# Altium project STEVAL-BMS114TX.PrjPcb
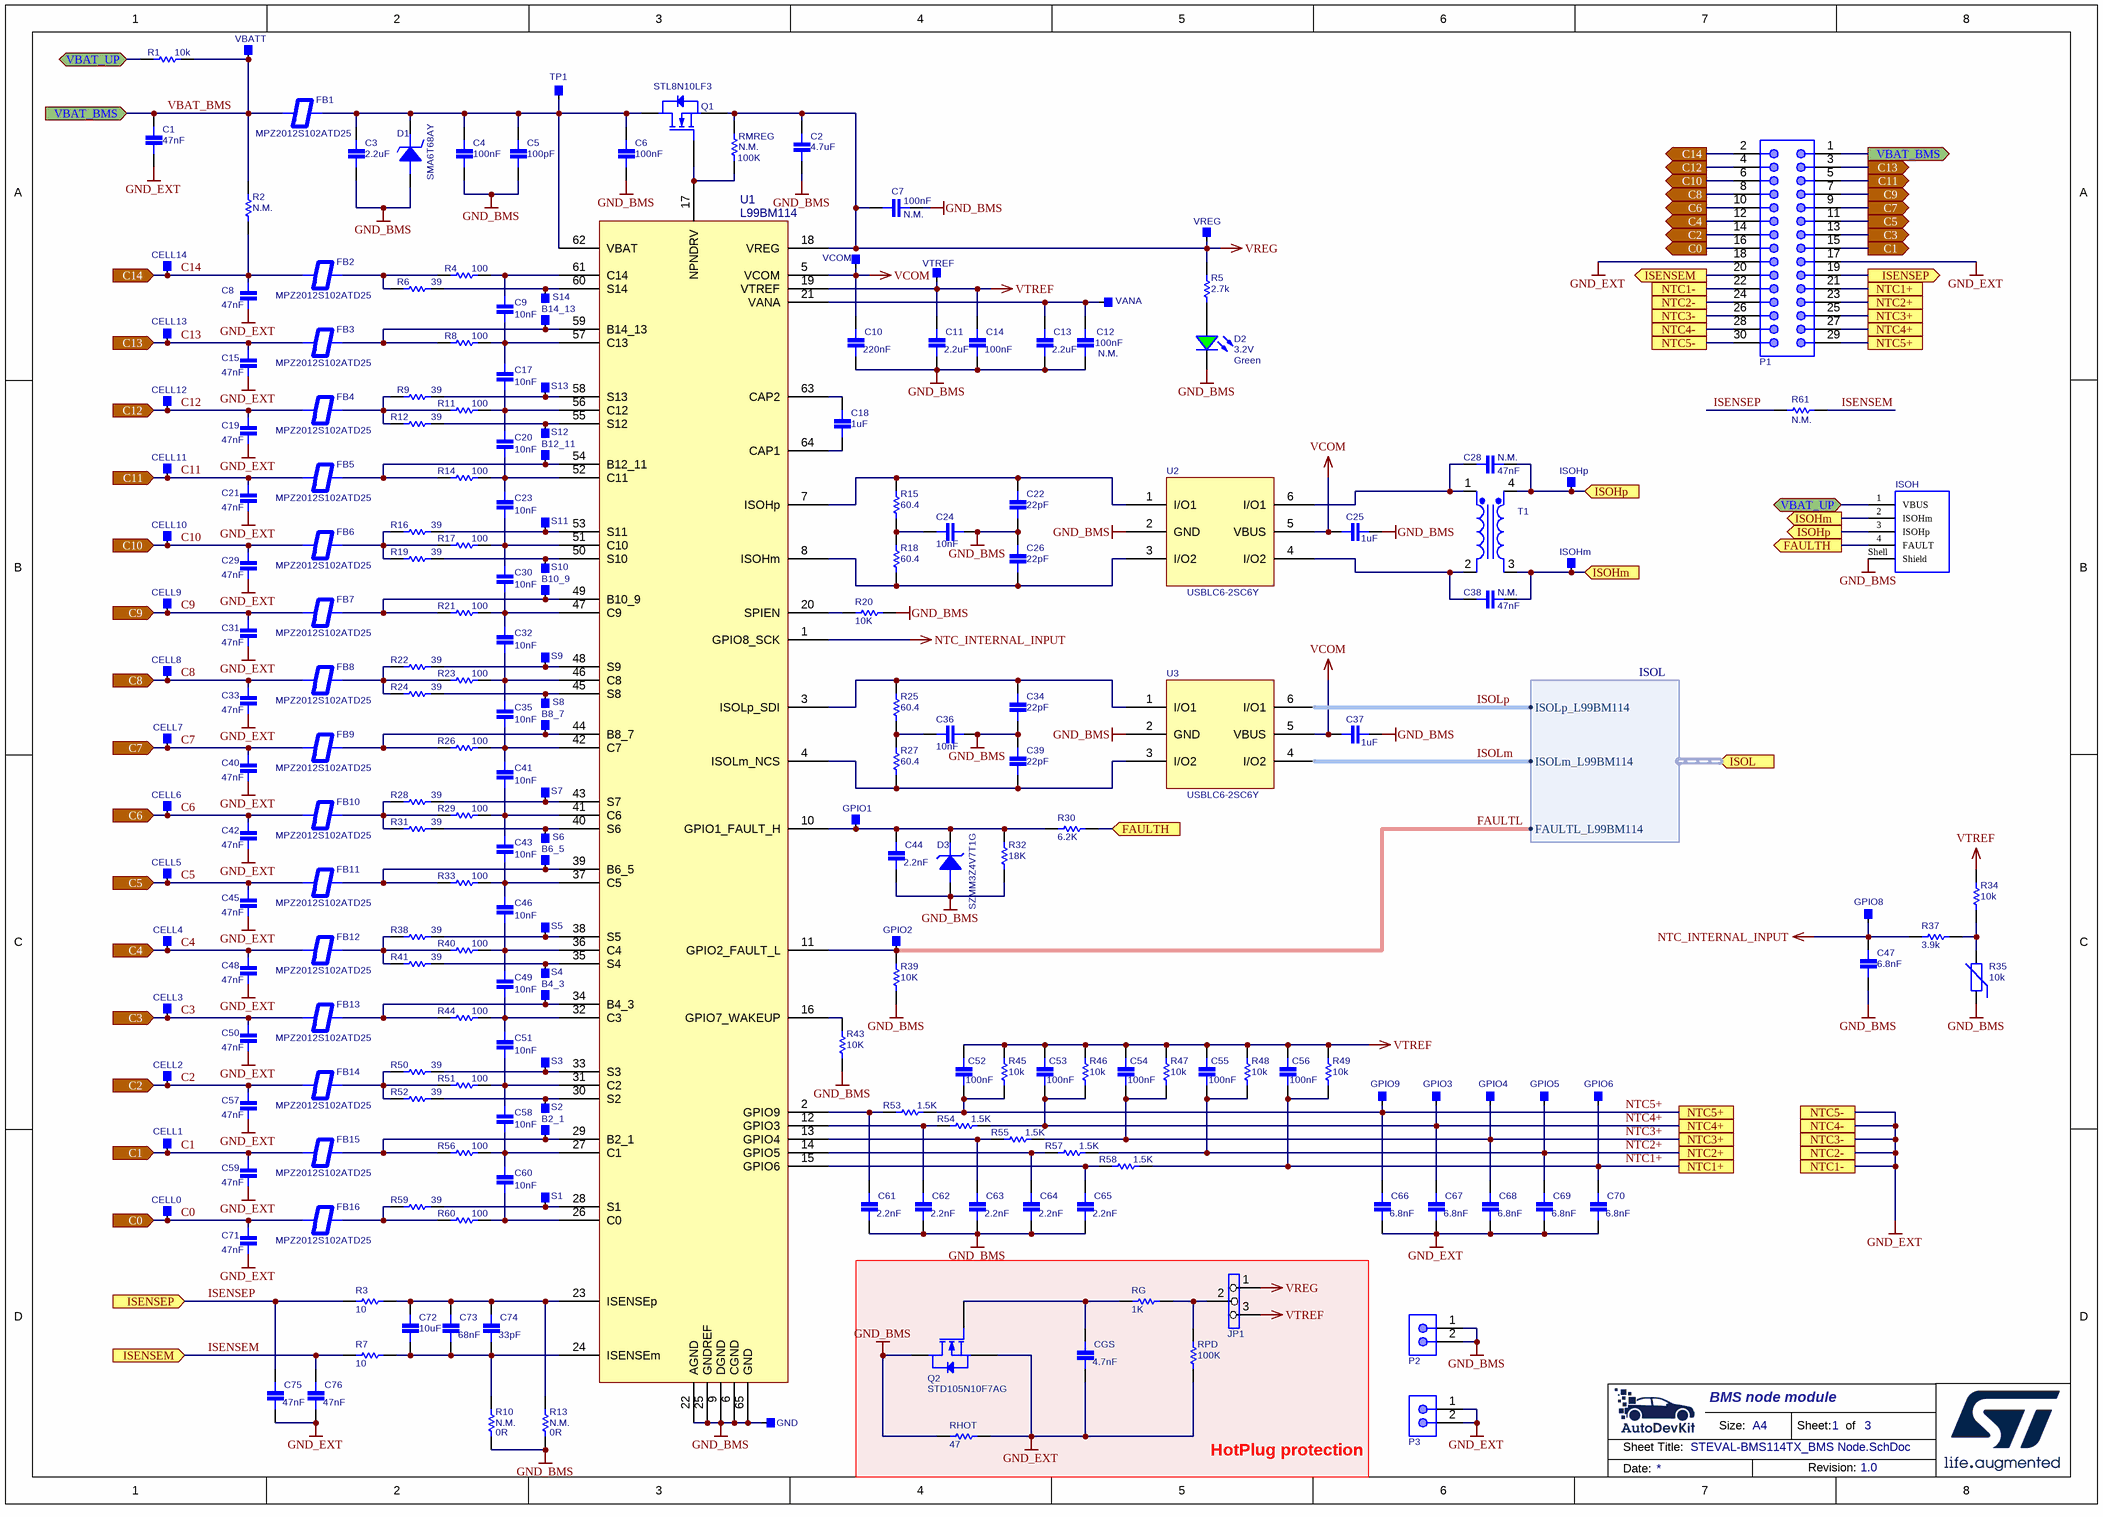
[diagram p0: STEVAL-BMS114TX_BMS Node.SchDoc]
3 sheets, 306 parts. Net scope: global (net labels, ports and power ports of the same name join across sheets).
Board file: STEVAL-BMS114TX.PcbDoc
Sheets:
  STEVAL-BMS114TX_BMS Node.SchDoc
  STEVAL-BMS114TX_Isolated SPI & MCU interface.SchDoc
  [3]Loghi.SchDoc

## Sheet STEVAL-BMS114TX_BMS Node.SchDoc: BMS node module
size A3; Organization: Altium Limited; Address1: L3, 12a Rodborough Rd; Address2: Frenchs Forest; Address3: NSW; Address4: Australia 2086; Revision: 1.0; SheetNumber: 1; SheetTotal: 3

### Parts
B2_1  TEST POINT_TH  [TP_0.7mm]  (value not drawn)  (no BOM)
B4_3  TEST POINT_TH  [TP_0.7mm]  (value not drawn)  (no BOM)
B6_5  TEST POINT_TH  [TP_0.7mm]  (value not drawn)  (no BOM)
B8_7  TEST POINT_TH  [TP_0.7mm]  (value not drawn)  (no BOM)
B10_9  TEST POINT_TH  [TP_0.7mm]  (value not drawn)  (no BOM)
B12_11  TEST POINT_TH  [TP_0.7mm]  (value not drawn)  (no BOM)
B14_13  TEST POINT_TH  [TP_0.7mm]  (value not drawn)  (no BOM)
C1  value 47nF  [0603C]  (hidden comment: Capacitor_0603)
C2  value 4.7uF  [1206C]  (hidden comment: Capacitor_1206)
C3  value 2.2uF  [1210C]  (hidden comment: Capacitor_1210)
C4  value 100nF  [0603C]  (hidden comment: Capacitor_0603)
C5  value 100pF  [0603C]  (hidden comment: Capacitor_0603)
C6  value 100nF  [0603C]  (hidden comment: Capacitor_0603)
C7  100nF  value N.M.  [0603C]
C8  value 47nF  [0603C]  (hidden comment: Capacitor_0603)
C9  value 10nF  [0603C]  (hidden comment: Capacitor_0603)
C10  value 220nF  [0603C]  (hidden comment: Capacitor_0603)
C11  value 2.2uF  [0805C]  (hidden comment: Capacitor_0805)
C12  100nF  value N.M.  [0603C]
C13  value 2.2uF  [0805C]  (hidden comment: Capacitor_0805)
C14  value 100nF  [0603C]  (hidden comment: Capacitor_0603)
C15  value 47nF  [0603C]  (hidden comment: Capacitor_0603)
C17  value 10nF  [0603C]  (hidden comment: Capacitor_0603)
C18  value 1uF  [0805C]  (hidden comment: Capacitor_0805)
C19  value 47nF  [0603C]  (hidden comment: Capacitor_0603)
C20  value 10nF  [0603C]  (hidden comment: Capacitor_0603)
C21  value 47nF  [0603C]  (hidden comment: Capacitor_0603)
C22  value 22pF  [0603C]  (hidden comment: Capacitor_0603)
C23  value 10nF  [0603C]  (hidden comment: Capacitor_0603)
C24  value 10nF  [0603C]  (hidden comment: Capacitor_0603)
C25  value 1uF  [0805C]  (hidden comment: Capacitor_0805)
C26  value 22pF  [0603C]  (hidden comment: Capacitor_0603)
C28  47nF  value N.M.  [1206C]
C29  value 47nF  [0603C]  (hidden comment: Capacitor_0603)
C30  value 10nF  [0603C]  (hidden comment: Capacitor_0603)
C31  value 47nF  [0603C]  (hidden comment: Capacitor_0603)
C32  value 10nF  [0603C]  (hidden comment: Capacitor_0603)
C33  value 47nF  [0603C]  (hidden comment: Capacitor_0603)
C34  value 22pF  [0603C]  (hidden comment: Capacitor_0603)
C35  value 10nF  [0603C]  (hidden comment: Capacitor_0603)
C36  value 10nF  [0603C]  (hidden comment: Capacitor_0603)
C37  value 1uF  [0805C]  (hidden comment: Capacitor_0805)
C38  47nF  value N.M.  [1206C]
C39  value 22pF  [0603C]  (hidden comment: Capacitor_0603)
C40  value 47nF  [0603C]  (hidden comment: Capacitor_0603)
C41  value 10nF  [0603C]  (hidden comment: Capacitor_0603)
C42  value 47nF  [0603C]  (hidden comment: Capacitor_0603)
C43  value 10nF  [0603C]  (hidden comment: Capacitor_0603)
C44  value 2.2nF  [0603C]  (hidden comment: Capacitor_0603)
C45  value 47nF  [0603C]  (hidden comment: Capacitor_0603)
C46  value 10nF  [0603C]  (hidden comment: Capacitor_0603)
C47  value 6.8nF  [0603C]  (hidden comment: Capacitor_0603)
C48  value 47nF  [0603C]  (hidden comment: Capacitor_0603)
C49  value 10nF  [0603C]  (hidden comment: Capacitor_0603)
C50  value 47nF  [0603C]  (hidden comment: Capacitor_0603)
C51  value 10nF  [0603C]  (hidden comment: Capacitor_0603)
C52  value 100nF  [0603C]  (hidden comment: Capacitor_0603)
C53  value 100nF  [0603C]  (hidden comment: Capacitor_0603)
C54  value 100nF  [0603C]  (hidden comment: Capacitor_0603)
C55  value 100nF  [0603C]  (hidden comment: Capacitor_0603)
C56  value 100nF  [0603C]  (hidden comment: Capacitor_0603)
C57  value 47nF  [0603C]  (hidden comment: Capacitor_0603)
C58  value 10nF  [0603C]  (hidden comment: Capacitor_0603)
C59  value 47nF  [0603C]  (hidden comment: Capacitor_0603)
C60  value 10nF  [0603C]  (hidden comment: Capacitor_0603)
C61  value 2.2nF  [0603C]  (hidden comment: Capacitor_0603)
C62  value 2.2nF  [0603C]  (hidden comment: Capacitor_0603)
C63  value 2.2nF  [0603C]  (hidden comment: Capacitor_0603)
C64  value 2.2nF  [0603C]  (hidden comment: Capacitor_0603)
C65  value 2.2nF  [0603C]  (hidden comment: Capacitor_0603)
C66  value 6.8nF  [0603C]  (hidden comment: Capacitor_0603)
C67  value 6.8nF  [0603C]  (hidden comment: Capacitor_0603)
C68  value 6.8nF  [0603C]  (hidden comment: Capacitor_0603)
C69  value 6.8nF  [0603C]  (hidden comment: Capacitor_0603)
C70  value 6.8nF  [0603C]  (hidden comment: Capacitor_0603)
C71  value 47nF  [0603C]  (hidden comment: Capacitor_0603)
C72  value 10uF  [1210C]  (hidden comment: Capacitor_1210)
C73  value 68nF  [0603C]  (hidden comment: Capacitor_0603)
C74  value 33pF  [0603C]  (hidden comment: Capacitor_0603)
C75  value 47nF  [0603C]  (hidden comment: Capacitor_0603)
C76  value 47nF  [0603C]  (hidden comment: Capacitor_0603)
CELL0  TEST POINT_TH  [TP_0.7mm]  (value not drawn)  (no BOM)
CELL1  TEST POINT_TH  [TP_0.7mm]  (value not drawn)  (no BOM)
CELL2  TEST POINT_TH  [TP_0.7mm]  (value not drawn)  (no BOM)
CELL3  TEST POINT_TH  [TP_0.7mm]  (value not drawn)  (no BOM)
CELL4  TEST POINT_TH  [TP_0.7mm]  (value not drawn)  (no BOM)
CELL5  TEST POINT_TH  [TP_0.7mm]  (value not drawn)  (no BOM)
CELL6  TEST POINT_TH  [TP_0.7mm]  (value not drawn)  (no BOM)
CELL7  TEST POINT_TH  [TP_0.7mm]  (value not drawn)  (no BOM)
CELL8  TEST POINT_TH  [TP_0.7mm]  (value not drawn)  (no BOM)
CELL9  TEST POINT_TH  [TP_0.7mm]  (value not drawn)  (no BOM)
CELL10  TEST POINT_TH  [TP_0.7mm]  (value not drawn)  (no BOM)
CELL11  TEST POINT_TH  [TP_0.7mm]  (value not drawn)  (no BOM)
CELL12  TEST POINT_TH  [TP_0.7mm]  (value not drawn)  (no BOM)
CELL13  TEST POINT_TH  [TP_0.7mm]  (value not drawn)  (no BOM)
CELL14  TEST POINT_TH  [TP_0.7mm]  (value not drawn)  (no BOM)
CGS  value 4.7nF  [0603C]  (hidden comment: Capacitor_0603)
D1  SMA6T68AY  [SMA]
D2  value Green  Voltage: 3.2V  [LED_0805]  (hidden comment: LED_Green)
D3  SZMM3Z4V7T1G  [SOD-323]
FB1  MPZ2012S102ATD25  [0805L]
FB2  MPZ2012S102ATD25  [0805L]
FB3  MPZ2012S102ATD25  [0805L]
FB4  MPZ2012S102ATD25  [0805L]
FB5  MPZ2012S102ATD25  [0805L]
FB6  MPZ2012S102ATD25  [0805L]
FB7  MPZ2012S102ATD25  [0805L]
FB8  MPZ2012S102ATD25  [0805L]
FB9  MPZ2012S102ATD25  [0805L]
FB10  MPZ2012S102ATD25  [0805L]
FB11  MPZ2012S102ATD25  [0805L]
FB12  MPZ2012S102ATD25  [0805L]
FB13  MPZ2012S102ATD25  [0805L]
FB14  MPZ2012S102ATD25  [0805L]
FB15  MPZ2012S102ATD25  [0805L]
FB16  MPZ2012S102ATD25  [0805L]
GND  TEST POINT_TH  [TP_0.7mm]  (value not drawn)  (no BOM)
GPIO1  TEST POINT_TH  [TP_0.7mm]  (value not drawn)  (no BOM)
GPIO2  TEST POINT_TH  [TP_0.7mm]  (value not drawn)  (no BOM)
GPIO3  TEST POINT_TH  [TP_0.7mm]  (value not drawn)  (no BOM)
GPIO4  TEST POINT_TH  [TP_0.7mm]  (value not drawn)  (no BOM)
GPIO5  TEST POINT_TH  [TP_0.7mm]  (value not drawn)  (no BOM)
GPIO6  TEST POINT_TH  [TP_0.7mm]  (value not drawn)  (no BOM)
GPIO8  TEST POINT_TH  [TP_0.7mm]  (value not drawn)  (no BOM)
GPIO9  TEST POINT_TH  [TP_0.7mm]  (value not drawn)  (no BOM)
ISOH  USB 2.0 Type A Receptacle_for BMS  [USB_2_0_Type_A_Receptacle_modify]  (value not drawn)
ISOHm  TEST POINT_TH  [TP_0.7mm]  (value not drawn)  (no BOM)
ISOHp  TEST POINT_TH  [TP_0.7mm]  (value not drawn)  (no BOM)
JP1  Header 3x1  [SIL_3x1]  (value not drawn)
P1  Con 30p_2.00  [Con 30p_2.00]  (value not drawn)
P2  GND_BMS  [SIL_2x1]  (value not drawn)
P3  GND_EXT  [SIL_2x1]  (value not drawn)
Q1  STL8N10LF3  [PowerFLAT 5x6_WF type C]
Q2  STD105N10F7AG  [DPAK_TO-252]
R1  value 10k  [1206R]  (hidden comment: Resistor_1206)
R2  value N.M.  [0805R]  (hidden comment: Resistor_0805)
R3  value 10  [0603R]  (hidden comment: Res 10)
R4  value 100  [0603R]  (hidden comment: Resistor_0805)
R5  value 2.7k  [0603R]  (hidden comment: Resistor_0603)
R6  value 39  [2010R]  (hidden comment: Resistor_2010)
R7  value 10  [0603R]  (hidden comment: Res 10)
R8  value 100  [0603R]  (hidden comment: Resistor_0805)
R9  value 39  [2010R]  (hidden comment: Resistor_2010)
R10  0R  value N.M.  [0603R]
R11  value 100  [0603R]  (hidden comment: Resistor_0805)
R12  value 39  [2010R]  (hidden comment: Resistor_2010)
R13  0R  value N.M.  [0603R]
R14  value 100  [0603R]  (hidden comment: Resistor_0805)
R15  value 60.4  [0603R]  (hidden comment: Resistor_0603)
R16  value 39  [2010R]  (hidden comment: Resistor_2010)
R17  value 100  [0603R]  (hidden comment: Resistor_0805)
R18  value 60.4  [0603R]  (hidden comment: Resistor_0603)
R19  value 39  [2010R]  (hidden comment: Resistor_2010)
R20  value 10K  [0603R]  (hidden comment: Resistor_0603)
R21  value 100  [0603R]  (hidden comment: Resistor_0805)
R22  value 39  [2010R]  (hidden comment: Resistor_2010)
R23  value 100  [0603R]  (hidden comment: Resistor_0805)
R24  value 39  [2010R]  (hidden comment: Resistor_2010)
R25  value 60.4  [0603R]  (hidden comment: Resistor_0603)
R26  value 100  [0603R]  (hidden comment: Resistor_0805)
R27  value 60.4  [0603R]  (hidden comment: Resistor_0603)
R28  value 39  [2010R]  (hidden comment: Resistor_2010)
R29  value 100  [0603R]  (hidden comment: Resistor_0805)
R30  value 6.2K  [0805R]  (hidden comment: Resistor_0805)
R31  value 39  [2010R]  (hidden comment: Resistor_2010)
R32  value 18K  [0603R]  (hidden comment: Resistor_0603)
R33  value 100  [0603R]  (hidden comment: Resistor_0805)
R34  value 10k  [0805R]  (hidden comment: Resistor_0805)
R35  value 10k  [0603R]  (hidden comment: Thermistor NTC_0603)
R37  value 3.9k  [0603R]  (hidden comment: Resistor_0603)
R38  value 39  [2010R]  (hidden comment: Resistor_2010)
R39  value 10K  [0603R]  (hidden comment: Resistor_0603)
R40  value 100  [0603R]  (hidden comment: Resistor_0805)
R41  value 39  [2010R]  (hidden comment: Resistor_2010)
R43  value 10K  [0603R]  (hidden comment: Resistor_0603)
R44  value 100  [0603R]  (hidden comment: Resistor_0805)
R45  value 10k  [0805R]  (hidden comment: Resistor_0805)
R46  value 10k  [0805R]  (hidden comment: Resistor_0805)
R47  value 10k  [0805R]  (hidden comment: Resistor_0805)
R48  value 10k  [0805R]  (hidden comment: Resistor_0805)
R49  value 10k  [0805R]  (hidden comment: Resistor_0805)
R50  value 39  [2010R]  (hidden comment: Resistor_2010)
R51  value 100  [0603R]  (hidden comment: Resistor_0805)
R52  value 39  [2010R]  (hidden comment: Resistor_2010)
R53  value 1.5K  [2010R]  (hidden comment: Resistor_2010)
R54  value 1.5K  [2010R]  (hidden comment: Resistor_2010)
R55  value 1.5K  [2010R]  (hidden comment: Resistor_2010)
R56  value 100  [0603R]  (hidden comment: Resistor_0805)
R57  value 1.5K  [2010R]  (hidden comment: Resistor_2010)
R58  value 1.5K  [2010R]  (hidden comment: Resistor_2010)
R59  value 39  [2010R]  (hidden comment: Resistor_2010)
R60  value 100  [0603R]  (hidden comment: Resistor_0805)
R61  N.M.  [2512R]
RG  value 1K  [0603R]  (hidden comment: Resistor_0603)
RHOT  value 47  [2512R]  (hidden comment: Resistor_2512)
RMREG  100K  value N.M.  [0603R]
RPD  value 100K  [0603R]  (hidden comment: Resistor_0603)
S1  TEST POINT_TH  [TP_0.7mm]  (value not drawn)  (no BOM)
S2  TEST POINT_TH  [TP_0.7mm]  (value not drawn)  (no BOM)
S3  TEST POINT_TH  [TP_0.7mm]  (value not drawn)  (no BOM)
S4  TEST POINT_TH  [TP_0.7mm]  (value not drawn)  (no BOM)
S5  TEST POINT_TH  [TP_0.7mm]  (value not drawn)  (no BOM)
S6  TEST POINT_TH  [TP_0.7mm]  (value not drawn)  (no BOM)
S7  TEST POINT_TH  [TP_0.7mm]  (value not drawn)  (no BOM)
S8  TEST POINT_TH  [TP_0.7mm]  (value not drawn)  (no BOM)
S9  TEST POINT_TH  [TP_0.7mm]  (value not drawn)  (no BOM)
S10  TEST POINT_TH  [TP_0.7mm]  (value not drawn)  (no BOM)
S11  TEST POINT_TH  [TP_0.7mm]  (value not drawn)  (no BOM)
S12  TEST POINT_TH  [TP_0.7mm]  (value not drawn)  (no BOM)
S13  TEST POINT_TH  [TP_0.7mm]  (value not drawn)  (no BOM)
S14  TEST POINT_TH  [TP_0.7mm]  (value not drawn)  (no BOM)
T1  WE - 74941000  [ESMIT4180]  (value not drawn)
TP1  TEST POINT_TH  [TP_0.7mm]  (value not drawn)  (no BOM)
U1  L99BM114  [TQFP64]
U2  USBLC6-2SC6Y  [SOT23-6L]
U3  USBLC6-2SC6Y  [SOT23-6L]
VANA  TEST POINT_TH  [TP_0.7mm]  (value not drawn)  (no BOM)
VBATT  TEST POINT_TH  [TP_0.7mm]  (value not drawn)  (no BOM)
VCOM  TEST POINT_TH  [TP_0.7mm]  (value not drawn)  (no BOM)
VREG  TEST POINT_TH  [TP_0.7mm]  (value not drawn)  (no BOM)
VTREF  TEST POINT_TH  [TP_0.7mm]  (value not drawn)  (no BOM)

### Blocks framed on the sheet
HotPlug protection: CGS JP1 Q2 RG RHOT RPD

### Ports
C0 (in), C0 (out), C1 (in), C1 (out), C2 (in), C2 (out), C3 (in), C3 (out), C4 (in), C4 (out), C5 (in), C5 (out), C6 (in), C6 (out), C7 (in), C7 (out), C8 (in), C8 (out), C9 (in), C9 (out), C10 (in), C10 (out), C11 (in), C11 (out), C12 (in), C12 (out), C13 (in), C13 (out), C14 (in), C14 (out), FAULTH (in), FAULTH (out), ISENSEM (in), ISENSEM (out), ISENSEP (in), ISENSEP (out), ISOHm (in), ISOHm (out), ISOHp (in), ISOHp (out), ISOL (in, harness ISOL), NTC1+, NTC1-, NTC2+, NTC2-, NTC3+, NTC3-, NTC4+, NTC4-, NTC5+, NTC5-, VBAT_BMS (in), VBAT_BMS (out), VBAT_UP (bidir)

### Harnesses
ISOL: ISOLp_L99BM114, ISOLm_L99BM114, FAULTL_L99BM114

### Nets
GND_BMS: C2.1 C3.1 C4.1 C5.1 C6.1 C7.1 C10.1 C11.1 C12.1 C13.1 C14.1 C22.1 C24.2 C25.2 C26.2 C34.1 C36.2 C37.2 C39.2 C44.1 C47.1 C61.1 C62.1 C63.1 C64.1 C65.1 D1.1(ANODE) D2.2(K) D3.1(A) GND.1(TP) ISOH.Shell(Shield) P2.1 P2.2 Q2.2(D) R10.2 R13.2 R20.2 R32.1 R35.1 R39.2 R43.2 RHOT.1 U1.6(CGND) U1.9(DGND) U1.22(AGND) U1.25(GNDREF) U1.65(GND) U2.2(GND) U3.2(GND)
GND_EXT: C1.1 C8.1 C15.1 C19.1 C21.1 C29.1 C31.1 C33.1 C40.1 C42.1 C45.1 C48.1 C50.1 C57.1 C59.1 C66.1 C67.1 C68.1 C69.1 C70.1 C71.1 C75.1 C76.1 CGS.1 P1.17 P1.18 P1.22 P1.24 P1.26 P1.28 P1.30 P3.1 P3.2 Q2.3(S) RHOT.2 RPD.1 ; port NTC4-, port NTC3-, port NTC2-, port NTC1-, port NTC5-
NTC_INTERNAL_INPUT: C47.2 GPIO8.1(TP) R37.1 U1.1(GPIO8_SCK)
VCOM: C10.2 C25.1 C37.1 U1.5(VCOM) U2.5(VBUS) U3.5(VBUS) VCOM.1(TP)
VREG: C2.2 C7.2 JP1.1 Q1.1,2,3(S) R5.2 RMREG.2 U1.18(VREG) VREG.1(TP)
VTREF: C11.2 C14.2 C52.2 C53.2 C54.2 C55.2 C56.2 JP1.3 R34.2 R45.2 R46.2 R47.2 R48.2 R49.2 U1.19(VTREF) VTREF.1(TP)
C0: C71.2 CELL0.1(TP) FB16.1 P1.16 ; port C0
C1: C59.2 CELL1.1(TP) FB15.1 P1.15 ; port C1
C2: C57.2 CELL2.1(TP) FB14.1 P1.14 ; port C2
C3: C50.2 CELL3.1(TP) FB13.1 P1.13 ; port C3
C4: C48.2 CELL4.1(TP) FB12.1 P1.12 ; port C4
C5: C45.2 CELL5.1(TP) FB11.1 P1.11 ; port C5
C6: C42.2 CELL6.1(TP) FB10.1 P1.10 ; port C6
C7: C40.2 CELL7.1(TP) FB9.1 P1.9 ; port C7
C8: C33.2 CELL8.1(TP) FB8.1 P1.8 ; port C8
C9: C31.2 CELL9.1(TP) FB7.1 P1.7 ; port C9
C10: C29.2 CELL10.1(TP) FB6.1 P1.6 ; port C10
C11: C21.2 CELL11.1(TP) FB5.1 P1.5 ; port C11
C12: C19.2 CELL12.1(TP) FB4.1 P1.4 ; port C12
C13: C15.2 CELL13.1(TP) FB3.1 P1.3 ; port C13
C14: C8.2 CELL14.1(TP) FB2.1 P1.2 R2.1 ; port C14
FAULTL: GPIO2.1(TP) R39.1 U1.11(GPIO2_FAULT_L) ; port ISOL.FAULTL_L99BM114
ISENSEM: C76.2 P1.20 R7.1 R61.2 ; port ISENSEM
ISENSEP: C75.2 P1.19 R3.1 R61.1 ; port ISENSEP
ISOLm: U3.4(I/O2) ; port ISOL.ISOLm_L99BM114
ISOLp: U3.6(I/O1) ; port ISOL.ISOLp_L99BM114
NTC1+: C56.1 C70.2 GPIO6.1(TP) P1.21 R49.1 R58.2 ; port NTC1+
NTC2+: C55.1 C69.2 GPIO5.1(TP) P1.23 R48.1 R57.2 ; port NTC2+
NTC3+: C54.1 C68.2 GPIO4.1(TP) P1.25 R47.1 R55.2 ; port NTC3+
NTC4+: C53.1 C67.2 GPIO3.1(TP) P1.27 R46.1 R54.2 ; port NTC4+
NTC5+: C52.1 C66.2 GPIO9.1(TP) P1.29 R45.1 R53.2 ; port NTC5+
VBAT_BMS: C1.2 FB1.1 P1.1 R1.2 R2.2 VBATT.1(TP) ; port VBAT_BMS
NetB2_1_1: B2_1.1(TP) FB15.2 R56.1 U1.29(B2_1)
NetB4_3_1: B4_3.1(TP) FB13.2 R44.1 U1.34(B4_3)
NetB6_5_1: B6_5.1(TP) FB11.2 R33.1 U1.39(B6_5)
NetB8_7_1: B8_7.1(TP) FB9.2 R26.1 U1.44(B8_7)
NetB10_9_1: B10_9.1(TP) FB7.2 R21.1 U1.49(B10_9)
NetB12_11_1: B12_11.1(TP) FB5.2 R14.1 U1.54(B12_11)
NetB14_13_1: B14_13.1(TP) FB3.2 R8.1 U1.59(B14_13)
NetC3_2: C3.2 C4.2 C5.2 C6.2 D1.2(CATHODE) FB1.2 Q1.5,6,7,8(D) TP1.1(TP) U1.62(VBAT)
NetC9_1: C9.1 C17.2 R8.2 U1.57(C13)
NetC9_2: C9.2 R4.2 U1.61(C14)
NetC12_2: C12.2 C13.2 U1.21(VANA) VANA.1(TP)
NetC17_1: C17.1 C20.2 R11.2 U1.56(C12)
NetC18_1: C18.1 U1.64(CAP1)
NetC18_2: C18.2 U1.63(CAP2)
NetC20_1: C20.1 C23.2 R14.2 U1.52(C11)
NetC22_2: C22.2 R15.2 U1.7(ISOHp) U2.1(I/O1)
NetC23_1: C23.1 C30.2 R17.2 U1.51(C10)
NetC24_1: C24.1 R15.1 R18.2
NetC26_1: C26.1 R18.1 U1.8(ISOHm) U2.3(I/O2)
NetC28_1: C28.1 T1.1(Pri+) U2.6(I/O1)
NetC28_2: C28.2 ISOH.3(ISOHp) ISOHp.1(TP) T1.4(Sec-) ; port ISOHp
NetC30_1: C30.1 C32.2 R21.2 U1.47(C9)
NetC32_1: C32.1 C35.2 R23.2 U1.46(C8)
NetC34_2: C34.2 R25.2 U1.3(ISOLp_SDI) U3.1(I/O1)
NetC35_1: C35.1 C41.2 R26.2 U1.42(C7)
NetC36_1: C36.1 R25.1 R27.2
NetC38_1: C38.1 T1.2(Pri-) U2.4(I/O2)
NetC38_2: C38.2 ISOH.2(ISOHm) ISOHm.1(TP) T1.3(Sec+) ; port ISOHm
NetC39_1: C39.1 R27.1 U1.4(ISOLm_NCS) U3.3(I/O2)
NetC41_1: C41.1 C43.2 R29.2 U1.41(C6)
NetC43_1: C43.1 C46.2 R33.2 U1.37(C5)
NetC44_2: C44.2 D3.2(K) GPIO1.1(TP) R30.1 R32.2 U1.10(GPIO1_FAULT_H)
NetC46_1: C46.1 C49.2 R40.2 U1.36(C4)
NetC49_1: C49.1 C51.2 R44.2 U1.32(C3)
NetC51_1: C51.1 C58.2 R51.2 U1.31(C2)
NetC58_1: C58.1 C60.2 R56.2 U1.27(C1)
NetC60_1: C60.1 R60.2 U1.26(C0)
NetC61_2: C61.2 R53.1 U1.2(GPIO9)
NetC62_2: C62.2 R54.1 U1.12(GPIO3)
NetC63_2: C63.2 R55.1 U1.13(GPIO4)
NetC64_2: C64.2 R57.1 U1.14(GPIO5)
NetC65_2: C65.2 R58.1 U1.15(GPIO6)
NetC72_1: C72.1 C73.1 C74.1 R7.2 R10.1 U1.24(ISENSEm)
NetC72_2: C72.2 C73.2 C74.2 R3.2 R13.1 U1.23(ISENSEp)
NetCGS_2: CGS.2 Q2.1(G) RG.1
NetD2_1: D2.1(A) R5.1
NetFB2_2: FB2.2 R4.1 R6.1
NetFB4_2: FB4.2 R9.1 R11.1 R12.1
NetFB6_2: FB6.2 R16.1 R17.1 R19.1
NetFB8_2: FB8.2 R22.1 R23.1 R24.1
NetFB10_2: FB10.2 R28.1 R29.1 R31.1
NetFB12_2: FB12.2 R38.1 R40.1 R41.1
NetFB14_2: FB14.2 R50.1 R51.1 R52.1
NetFB16_2: FB16.2 R59.1 R60.1
NetISOH_1: ISOH.1(VBUS) R1.1 ; port VBAT_UP
NetISOH_4: ISOH.4(FAULT) R30.2 ; port FAULTH
NetJP1_2: JP1.2 RG.2 RPD.2
NetQ1_4: Q1.4(G) RMREG.1 U1.17(NPNDRV)
NetR6_2: R6.2 S14.1(TP) U1.60(S14)
NetR9_2: R9.2 S13.1(TP) U1.58(S13)
NetR12_2: R12.2 S12.1(TP) U1.55(S12)
NetR16_2: R16.2 S11.1(TP) U1.53(S11)
NetR19_2: R19.2 S10.1(TP) U1.50(S10)
NetR20_1: R20.1 U1.20(SPIEN)
NetR22_2: R22.2 S9.1(TP) U1.48(S9)
NetR24_2: R24.2 S8.1(TP) U1.45(S8)
NetR28_2: R28.2 S7.1(TP) U1.43(S7)
NetR31_2: R31.2 S6.1(TP) U1.40(S6)
NetR34_1: R34.1 R35.2 R37.2
NetR38_2: R38.2 S5.1(TP) U1.38(S5)
NetR41_2: R41.2 S4.1(TP) U1.35(S4)
NetR43_1: R43.1 U1.16(GPIO7_WAKEUP)
NetR50_2: R50.2 S3.1(TP) U1.33(S3)
NetR52_2: R52.2 S2.1(TP) U1.30(S2)
NetR59_2: R59.2 S1.1(TP) U1.28(S1)

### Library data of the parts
B2_1 B4_3 B6_5 B8_7 B10_9 B12_11 B14_13 CELL0-CELL14 GND GPIO1-GPIO6 GPIO8 GPIO9 ISOHm ISOHp S1-S14 TP1 VANA VBATT VCOM VREG VTREF = TEST POINT_TH: Test point_hole
C1 C8 C15 C19 C21 C29 C31 C33 C40 C42 C45 C48 C50 C57 C59 C71 C75 C76 = Cap 47nF: 0603 - 50V - X7R Class II; Manufacturer: WE; Part Number: 885012206093; Tollerance: ±10%
C2 = Cap 4.7uF: 1206 - 50V - X7R Class II; Manufacturer: WE; Part Number: 885012208094; Tollerance: ±10%
C3 = Cap 2.2uF_1210: 1210 - 100V - X7R Class II; Manufacturer: WE; Part Number: 885012209071; Tollerance: ±10%
C4 C6 C14 = Cap 100nF_0603: 0603 - 100V - X7R Class II; Manufacturer: WE; Part Number: 885012206120; Tollerance: ±10%
C5 = Cap 100pF_0603: 0603 - 100V - X7R Class II; Manufacturer: WE; Part Number: 885012206102; Tollerance: ±10%
C7 C12 = Cap N.M._0603: 0603 - xxV -  xxxx
C9 C17 C20 C23 C30 C32 C35 C41 C43 C46 C49 C51 C58 C60 = Cap 10nF_(bms): 0603 - 50V -  X7R Class II; Manufacturer: WE; Part Number: 885012206089; Tollerance: ±10%
C10 = Cap 220nF: 0603 - 50V - X7R Class II; Manufacturer: WE; Part Number: 885012206125; Tollerance: ±5%
C11 C13 = Cap 2.2uF: 0805 - 25V -  X7R Class II; Manufacturer: WE; Part Number: 885012207079; Tollerance: ±10%
C18 C25 C37 = Cap 1uF_0805: 0805 - 50V -  X7R Class II; Manufacturer: WE; Part Number: 885012207103; Tollerance: ±10%
C22 C26 C34 C39 = Cap 22pF: 0603 - 50V - NP0 Class I; Manufacturer: WE; Part Number: 885012006053; Tollerance: ±5%
C24 C36 = Cap 10nF: 0603 - 50V -  X7R Class II; Manufacturer: WE; Part Number: 885012206089; Tollerance: ±10%
C28 C38 = Cap N.M._1206: 1206 - xxV -  xxxx
C44 C61-C65 = Cap 2.2nF: 0603 - 50V - X7R Class II; Manufacturer: WE; Part Number: 885012206085; Tollerance: ±10%
C47 C66-C70 = Cap 6.8nF: 0603 - 50V - X7R Class II; Manufacturer: WE; Part Number: 885012206088; Tollerance: ±10%
C52-C56 = Cap 100nF: 0603 - 50V - X7R Class II; Manufacturer: WE; Part Number: 885012206095; Tollerance: ±10%
C72 = Cap 10uF: 1210 - 50V - X7R Class II; Manufacturer: WE; Part Number: 885012209073; Tollerance: ±10%
C73 = Cap 68nF: 0603 - 50V - X7R Class II; Manufacturer: WE; Part Number: 885012206094; Tollerance: ±10%
C74 = Cap 33pF: 0603 - 50V - NP0 Class I; Manufacturer: WE; Part Number: 885012006054; Tollerance: ±5%
CGS = Cap 4.7nF: 0603 - 50V - X7R Class II; Manufacturer: WE; Part Number: 885012206087; Tollerance: ±10%
D1 = SMA6T68AY: Automotive 600 W, 68V TVS in SMA; Manufacturer: STMicroelectronics; Power: 600W
D2 = LED_Green: 0805 - Led Green - 3.2V; Manufacturer: WE; Part Number: 150080GS75000
D3 = SZMM3Z4V7T1G: 4.7V Zener Voltage Regulators, 300mW; Manufacturer: Onsemi
FB1-FB16 = Ferrite Bead 1K_0805: Ferrite Beads Multi-Layer Power 1KOhm 25% 100MHz 1.5A 0.15Ohm DCR 0805; Manufacturer: TDK; Value: 1K@100MHz
ISOH = USB 2.0 Type A Receptacle: USB 2.0 Type A, Receptacle, Horizontal, THT; Manufacturer: WE; Part Number: 61400416021; Voltage: 30V; Current: 1.5A; Value: 61400416021
JP1 = Jumper 3p: THT Vertical 3 pins Header, Pitch 2.54 mm, Single Row; Manufacturer: WE; Part Number: 61300311121; Current: 3A; Voltage: 250VAC
P1 = Con 30p_2.00: 2.00mm - WR-WTB - Male Dual Row Horizontal Shrouded Header w. positive locking; Part Number: 62403021722; Manufacturer: WE; Voltage: 250V AC; Current: 3A
P2 P3 = Header 2p 2.54: 2.54mm - WR-PHD Pin Header, THT, pitch 2.54mm, Single Row, Vertical, 2p; Manufacturer: WE; Part Number: 61300211121; Voltage: 250V (AC); Current: 3A; Value: 61300211121
Q1 = STL8N10LF3: Automotive-grade N-channel 100 V, 25 mΩ typ., 7.8 A STripFET™ F3 Power MOSFET in a PowerFLAT™ 5x6 package; Manufacturer: STMicroelectronics; Voltage: 100V; Current: 7.8A; Power: 70W
Q2 = STD105N10F7AG: Automotive-grade N-channel 100 V, 6.8 mΩ typ., 80 A, / STripFET™ F7 Power MOSFET in a DPAK package; Manufacturer: STMicroelectronics; Voltage: 100V; Current: 80A; Power: 120W
R1 = Res 10K_1206: 1206 - ±1%  -  0.66W; Manufacturer: Panasonic; Part Number: ERJUP8F1002V
R2 = Res N.M._0805: 0805 - xx% - xxxx
R3 R7 = Res 10: 0603 - ±1%  -  0.25W; Manufacturer: Panasonic; Part Number: ERJPA3F10R0V
R4 R8 R11 R14 R17 R21 R23 R26 R29 R33 R40 R44 R51 R56 R60 = Res 100: 0603 - ±1%  -  0.25W; Manufacturer: Panasonic; Part Number: ERJPA3F1000V
R5 = Res 2.7k: 0603 - ±1%  -  0.125W; Manufacturer: Vishay; Part Number: MCT06030C2701FP500
R6 R9 R12 R16 R19 R22 R24 R28 R31 R38 R41 R50 R52 R59 = Res 39_2010: 2010 - ±1%  -  1.25W; Manufacturer: TE Connectivity; Part Number: CRGP2010F39R
R10 R13 RMREG = Res N.M._0603: 0603 - xx% - xxxx
R15 R18 R25 R27 = Res 60.4: 0603 - ±1%  -  0.1W; Manufacturer: Panasonic; Part Number: ERJ3EKF60R4V
R20 R39 R43 = Res 10K: 0603 - ±1%  -  0.2W; Manufacturer: Panasonic; Part Number: ERJP03F1002V
R30 = Res 6.2K_0805: 0805 - ±1%  -  0.5W; Manufacturer: Panasonic; Part Number: ERJP06F6201V; Power: 0.55W
R32 = Res 18K: 0603 - ±1%  -  0.2W; Manufacturer: Panasonic; Part Number: ERJP03F1802V
R34 R45-R49 = Res 10K_0805: 0805 - ±1%  -  0.5W; Manufacturer: Panasonic; Part Number: ERJP6WF1002V
R35 = NTC 10k_0603: 0603 - ±1%  -  0.1W; Manufacturer: TDK; Part Number: NTCG163JH103HTDS; Tollerance: ±3%
R37 = Res 3.9k: 0603 - ±1%  -  0.1W; Manufacturer: Panasonic; Part Number: ERJ3EKF3901V
R53-R55 R57 R58 = Res 1.5K_2010: 2010 - ±1%  -  2W; Manufacturer: TE Connectivity; Part Number: 35021K5FT
R61 = Res N.M.: xxxx- ±xx%  -  xxxx
RG = Res 1K: 0603 - ±1%  -  0.25W; Manufacturer: Panasonic; Part Number: ERJPA3F1001V
RHOT = Res 47_2512: 2512 - ±5%  -  1W; Manufacturer: TE Connectivity; Part Number: 352047RJT
RPD = Res 100K: 0603 - ±1%  -  0.25W; Manufacturer: Panasonic; Part Number: ERJP03F1003V
T1 = ESMIT-4180/A: Pulse Transformers 125uH
U1 = L9963E: Automotive chip for battery management applications with daisy chain up to 31 devices; Manufacturer: STMicroelectronics; Part Number: L99BM114-TR; Voltage: upto 64V
U2 U3 = USBLC6-2SC6Y: Automotive ESD protection for high speed interfaces.; Manufacturer: STMicroelectronics

## Sheet STEVAL-BMS114TX_Isolated SPI & MCU interface.SchDoc: Isolated SPI & MCU interface
size A4; Organization: Altium Limited; Address1: L3, 12a Rodborough Rd; Address2: Frenchs Forest; Address3: NSW; Address4: Australia 2086; Revision: 1.0; SheetNumber: 2; SheetTotal: 3
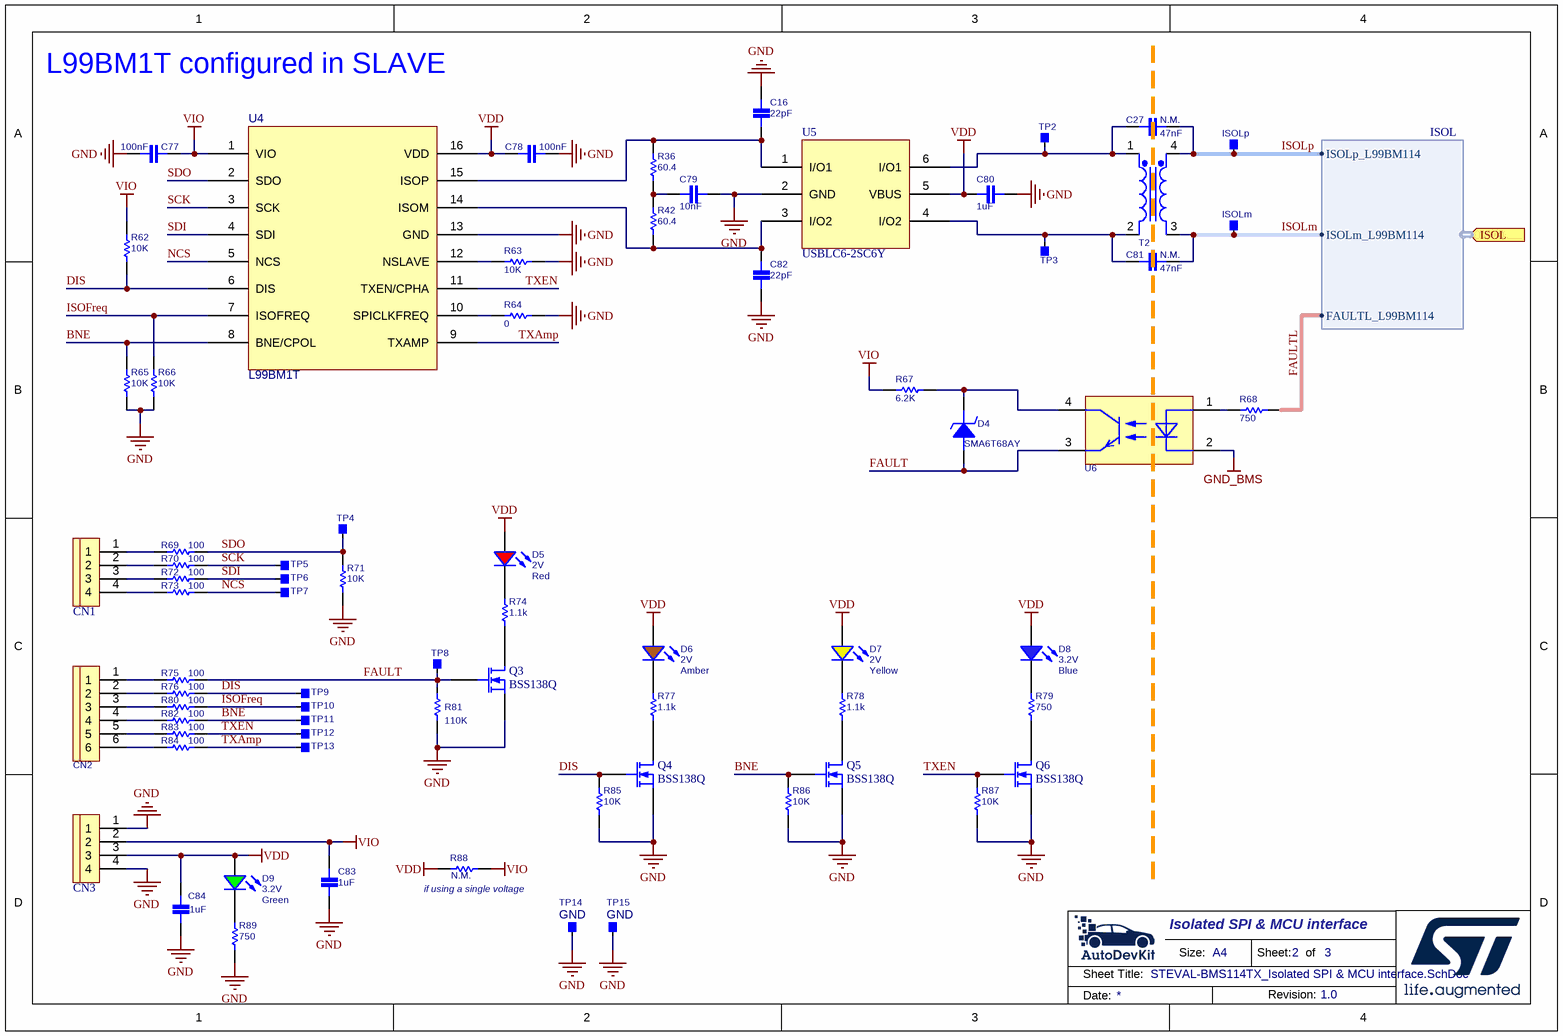
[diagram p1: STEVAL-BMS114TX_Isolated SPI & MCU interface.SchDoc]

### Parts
C16  value 22pF  [0603C]  (hidden comment: Cap 22pF)
C27  47nF  value N.M.  [1206C]
C77  value 100nF  [0603C]  (hidden comment: Capacitor_0603)
C78  value 100nF  [0603C]  (hidden comment: Capacitor_0603)
C79  value 10nF  [0603C]  (hidden comment: Cap 10nF)
C80  value 1uF  [0805C]  (hidden comment: Cap 1uF_1)
C81  47nF  value N.M.  [1206C]
C82  value 22pF  [0603C]  (hidden comment: Cap 22pF)
C83  value 1uF  [0805C]  (hidden comment: Cap 1uF_1)
C84  value 1uF  [0805C]  (hidden comment: Cap 1uF_1)
CN1  Con 4P  [KK254_4p]  (value not drawn)
CN2  Con 6P  [KK254_6P]  (value not drawn)
CN3  Con 4P  [KK254_4p]  (value not drawn)
D4  SMA6T68AY  [SMA]
D5  value Red  Voltage: 2V  [LED_0805]  (hidden comment: LED_Red)
D6  value Amber  Voltage: 2V  [LED_0805]  (hidden comment: LED_Amber)
D7  value Yellow  Voltage: 2V  [LED_0805]  (hidden comment: LED_Yellow)
D8  value Blue  Voltage: 3.2V  [LED_0805]  (hidden comment: LED_Blue)
D9  value Green  Voltage: 3.2V  [LED_0805]  (hidden comment: LED_Green)
ISOLm  TEST POINT_TH  [TP_0.7mm]  (value not drawn)  (no BOM)
ISOLp  TEST POINT_TH  [TP_0.7mm]  (value not drawn)  (no BOM)
Q3  value BSS138Q  [SOT-23]  (hidden comment: BSS138)
Q4  value BSS138Q  [SOT-23]  (hidden comment: BSS138)
Q5  value BSS138Q  [SOT-23]  (hidden comment: BSS138)
Q6  value BSS138Q  [SOT-23]  (hidden comment: BSS138)
R36  value 60.4  [0603R]  (hidden comment: Resistor_0603)
R42  value 60.4  [0603R]  (hidden comment: Resistor_0603)
R62  value 10K  [0603R]  (hidden comment: Resistor_0603)
R63  value 10K  [0603R]  (hidden comment: Resistor_0603)
R64  value 0  [0603R]  (hidden comment: Resistor_0603)
R65  value 10K  [0603R]  (hidden comment: Resistor_0603)
R66  value 10K  [0603R]  (hidden comment: Resistor_0603)
R67  value 6.2K  [0805R]  (hidden comment: Resistor_0805)
R68  value 750  [0603R]  (hidden comment: Resistor_0603)
R69  value 100  [0603R]  (hidden comment: Resistor_0805)
R70  value 100  [0603R]  (hidden comment: Resistor_0805)
R71  value 10K  [0603R]  (hidden comment: Resistor_0603)
R72  value 100  [0603R]  (hidden comment: Resistor_0805)
R73  value 100  [0603R]  (hidden comment: Resistor_0805)
R74  value 1.1k  [0603R]  (hidden comment: Resistor_0603)
R75  value 100  [0603R]  (hidden comment: Resistor_0805)
R76  value 100  [0603R]  (hidden comment: Resistor_0805)
R77  value 1.1k  [0603R]  (hidden comment: Resistor_0603)
R78  value 1.1k  [0603R]  (hidden comment: Resistor_0603)
R79  value 750  [0603R]  (hidden comment: Resistor_0603)
R80  value 100  [0603R]  (hidden comment: Resistor_0805)
R81  value 110K  [0603R]  (hidden comment: Resistor_0603)
R82  value 100  [0603R]  (hidden comment: Resistor_0805)
R83  value 100  [0603R]  (hidden comment: Resistor_0805)
R84  value 100  [0603R]  (hidden comment: Resistor_0805)
R85  value 10K  [0603R]  (hidden comment: Resistor_0603)
R86  value 10K  [0603R]  (hidden comment: Resistor_0603)
R87  value 10K  [0603R]  (hidden comment: Resistor_0603)
R88  if using a single voltage  value N.M.  [0805R]
R89  value 750  [0603R]  (hidden comment: Resistor_0603)
T2  WE - 74941000  [ESMIT4180]  (value not drawn)
TP2  TEST POINT  [TP_0.9mm]  (value not drawn)
TP3  TEST POINT  [TP_0.9mm]  (value not drawn)
TP4  SDO  [TP_0.9mm]  (value not drawn)
TP5  SCK  [TP_0.9mm]  (value not drawn)
TP6  SDI  [TP_0.9mm]  (value not drawn)
TP7  NCS  [TP_0.9mm]  (value not drawn)
TP8  FAULT  [TP_0.9mm]  (value not drawn)
TP9  DIS  [TP_0.9mm]  (value not drawn)
TP10  ISOFreq  [TP_0.9mm]  (value not drawn)
TP11  BNE  [TP_0.9mm]  (value not drawn)
TP12  TXEN  [TP_0.9mm]  (value not drawn)
TP13  TXAmp  [TP_0.9mm]  (value not drawn)
TP14  GND  [TP_0.9mm]
TP15  GND  [TP_0.9mm]
U4  L99BM1T  [SO16N]
U5  USBLC6-2SC6Y  [SOT23-6L]
U6  DC, 35V, 60mA  [WL-OCPT_SOP4]  (value not drawn)

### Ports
ISOL (in, harness ISOL)

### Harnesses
ISOL: ISOLp_L99BM114, ISOLm_L99BM114, FAULTL_L99BM114

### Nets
GND: C16.1 C77.1 C78.1 C79.1 C80.1 C82.1 C83.2 C84.1 CN3.1 CN3.4 Q3.2(S) Q4.2(S) Q5.2(S) Q6.2(S) R63.2 R64.1 R65.1 R66.1 R71.1 R81.1 R85.1 R86.1 R87.1 R89.1 TP14.1(TP) TP15.1(TP) U4.13(GND) U5.2(GND)
GND_BMS: U6.2(Cathode)
VDD: C78.2 C80.2 C84.2 CN3.3 D5.1(A) D6.1(A) D7.1(A) D8.1(A) D9.1(A) R88.2 U4.16(VDD) U5.5(VBUS)
VIO: C77.2 C83.1 CN3.2 R62.1 R67.1 R88.1 U4.1(VIO)
BNE: Q5.1(G) R65.2 R82.2 R86.2 TP11.1(TP) U4.8(BNE/CPOL)
DIS: Q4.1(G) R62.2 R76.2 R85.2 TP9.1(TP) U4.6(DIS)
FAULT: D4.1(ANODE) Q3.1(G) R75.2 R81.2 TP8.1(TP) U6.3(Emitter)
FAULTL: R68.2 ; port ISOL.FAULTL_L99BM114
ISOFreq: R66.2 R80.2 TP10.1(TP) U4.7(ISOFREQ)
ISOLm: C81.2 ISOLm.1(TP) T2.3(Sec+) ; port ISOL.ISOLm_L99BM114
ISOLp: C27.2 ISOLp.1(TP) T2.4(Sec-) ; port ISOL.ISOLp_L99BM114
NCS: R73.2 TP7.1(TP) U4.5(NCS)
SCK: R70.2 TP5.1(TP) U4.3(SCK)
SDI: R72.2 TP6.1(TP) U4.4(SDI)
SDO: R69.2 R71.2 TP4.1(TP) U4.2(SDO)
TXAmp: R84.2 TP13.1(TP) U4.9(TXAMP)
TXEN: Q6.1(G) R83.2 R87.2 TP12.1(TP) U4.11(TXEN/CPHA)
NetC16_2: C16.2 R36.1 U4.15(ISOP) U5.1(I/O1)
NetC27_1: C27.1 T2.1(Pri+) TP2.1(TP) U5.6(I/O1)
NetC79_2: C79.2 R36.2 R42.1
NetC81_1: C81.1 T2.2(Pri-) TP3.1(TP) U5.4(I/O2)
NetC82_2: C82.2 R42.2 U4.14(ISOM) U5.3(I/O2)
NetCN1_1: CN1.1 R69.1
NetCN1_2: CN1.2 R70.1
NetCN1_3: CN1.3 R72.1
NetCN1_4: CN1.4 R73.1
NetCN2_1: CN2.1 R75.1
NetCN2_2: CN2.2 R76.1
NetCN2_3: CN2.3 R80.1
NetCN2_4: CN2.4 R82.1
NetCN2_5: CN2.5 R83.1
NetCN2_6: CN2.6 R84.1
NetD4_2: D4.2(CATHODE) R67.2 U6.4(Collector)
NetD5_2: D5.2(K) R74.2
NetD6_2: D6.2(K) R77.2
NetD7_2: D7.2(K) R78.2
NetD8_2: D8.2(K) R79.2
NetD9_2: D9.2(K) R89.2
NetQ3_3: Q3.3(D) R74.1
NetQ4_3: Q4.3(D) R77.1
NetQ5_3: Q5.3(D) R78.1
NetQ6_3: Q6.3(D) R79.1
NetR63_1: R63.1 U4.12(NSLAVE)
NetR64_2: R64.2 U4.10(SPICLKFREQ)
NetR68_1: R68.1 U6.1(Anode)

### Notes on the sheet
- L99BM1T configured in SLAVE mode

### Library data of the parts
C16 C82 = Cap 22pF: 0603 - 50V - NP0 Class I; Manufacturer: WE; Part Number: 885012006053; Tollerance: 5%
C27 C81 = Cap N.M._1206: 1206 - xxV -  xxxx
C77 C78 = Cap 100nF: 0603 - 50V - X7R Class II; Manufacturer: WE; Part Number: 885012206095; Tollerance: 10%
C79 = Cap 10nF: 0603 - 50V -  X7R Class II; Manufacturer: WE; Part Number: 885012206089; Tollerance: 10%
C80 C83 C84 = Cap 1uF_1: 0805 - 50V -  X7R Class II; Manufacturer: WE; Part Number: 885012207103; Tollerance: 10%
CN1 CN3 = Con 4P: 2.54mm - 1 row - KK254 - Male; Part Number: 61900411121; Manufacturer: WE; Voltage: 250VAC; Current: 3A
CN2 = Con 6P: 2.54mm - 1 row - KK254 - Male; Part Number: 61900611121; Manufacturer: WE; Voltage: 250VAC; Current: 3A
D4 = SMA6T68AY: as D1 on sheet STEVAL-BMS114TX_BMS Node
D5 = LED_Red: 0805 - Led Red - 2V; Part Number: 150080RS75000; Manufacturer: WE
D6 = LED_Amber: 0805 - Led Amber - 2V; Manufacturer: WE; Part Number: 150080AS75000
D7 = LED_Yellow: 0805 - Led Yellow - 2V; Part Number: 150080YS75000; Manufacturer: WE
D8 = LED_Blue: 0805 - Led Blue - 3.2V; Part Number: 150080BS75000; Manufacturer: WE
D9 = LED_Green: 0805 - Led Green - 3.2V; Part Number: 150080GS75000; Manufacturer: WE
ISOLm ISOLp = TEST POINT_TH: Test point_hole
Q3-Q6 = BSS138: N-Channel Enhancement Mosfet; Manufacturer: NEXPERIA; Part Number: BSS138Q-7-F; Voltage: 50; Current: 0.2A; Power: 0.3W
R36 R42 = Res 60.4: as R15 on sheet STEVAL-BMS114TX_BMS Node
R62 R63 R65 R66 R71 R85-R87 = Res 10K: 0603 - ±1%  -  0.2W; Manufacturer: Panasonic; Part Number: ERJP03F1002V; Power: 1/4 W
R64 = Res 0: 0603 - ±1% - 0.1W; Manufacturer: Panasonic; Part Number: ERJ3GEY0R00V
R67 = Res 6.2K_0805: as R30 on sheet STEVAL-BMS114TX_BMS Node
R68 = Res 750: 0603 - ±0.5%  -  0.25W; Manufacturer: Panasonic; Part Number: ERJUP3D7500V
R69 R70 R72 R73 R75 R76 R80 R82-R84 = Res 100: 0603 - ±1%  -  0.25W; Manufacturer: Panasonic; Part Number: ERJPA3F1000V; Power: 1/4 W
R74 R77 R78 = Res 1.1k: 0603 - ±1%  -  0.25W; Manufacturer: Panasonic; Part Number: ERJPA3F1101V
R79 R89 = Res 750: 0603 - ±1%  -  0.25W; Manufacturer: Panasonic; Part Number: ERJUP3D7500V; Tollerance: ±0.5%
R81 = Res 110K: 0603 - ±1%  -  0.25W; Manufacturer: Panasonic; Part Number: ERJPA3F1103V
R88 = Res N.M.: xxxx - xx% - xxxx
T2 = ESMIT-4180/A: Pulse Transformers 125uH
TP4-TP15 = TEST POINT
U4 = L9963T: Automotive general purpose SPI to isolated SPI transceiver; Part Number: L99BM1T-TR; Manufacturer: STMicroelectronics; Voltage: 5V
U5 = USBLC6-2SC6Y: as U2 on sheet STEVAL-BMS114TX_BMS Node
U6 = 140357145300: WL-OCPT Optocoupler Phototransistor, SOP4, 1 Channel, DC, 35V, 60mA; Manufacturer: WE

## Sheet [3]Loghi.SchDoc: Loghi
size A4; Organization: Altium Limited; Address1: L3, 12a Rodborough Rd; Address2: Frenchs Forest; Address3: NSW; Address4: Australia 2086; Revision: 1.0; SheetNumber: 3; SheetTotal: 3
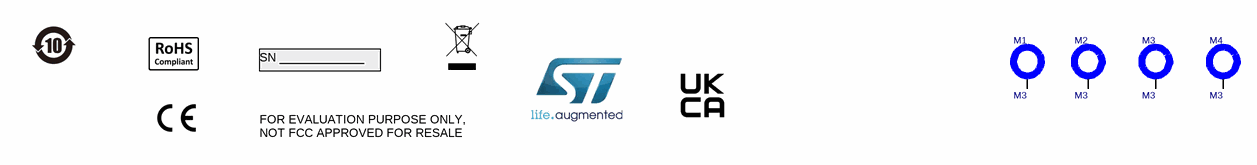
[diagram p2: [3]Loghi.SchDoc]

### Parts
M1  value M3  [M3]  (hidden comment: Hole 3mm)  (no BOM)
M2  value M3  [M3]  (hidden comment: Hole 3mm)  (no BOM)
M3  value M3  [M3]  (hidden comment: Hole 3mm)  (no BOM)
M4  value M3  [M3]  (hidden comment: Hole 3mm)  (no BOM)
text1  Label_China RoHS  [LOGO CHINA ROHS 10]  (value not drawn)  (no BOM)
text2  Label_RoHS  [LOGO RoHS - 3]  (value not drawn)  (no BOM)
text3  Label_SERIAL NUMBER  [LOGO SERIAL NUMBER]  (value not drawn)  (no BOM)
text4  Label_Weee symbol  [LOGO CESTINO]  (value not drawn)  (no BOM)
text5  Label_ST LOGO  [LogoST]  (value not drawn)  (no BOM)
text6  Label_UKCA  [LOGO UKCA]  (value not drawn)  (no BOM)
text7  Label_CE  [LOGO CE]  (value not drawn)  (no BOM)
text9  Label_FOR EVALUATION ...  [LOGO FOR EVALUATION ...]  (value not drawn)  (no BOM)

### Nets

Not connected (* = marked no-connect by the designer): M1 1; M2 1; M3 1; M4 1

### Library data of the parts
M1-M4 = Screw_3mm: WA-SCRW Pan Head Screw w. cross slot M3; Manufacturer: WE; Part Number: 97790403111
text5 = Label_ST LOGO: ST logo

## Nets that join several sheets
GND_BMS: STEVAL-BMS114TX_BMS Node (49 pins), STEVAL-BMS114TX_Isolated SPI & MCU interface (U6.2)
FAULTL: STEVAL-BMS114TX_BMS Node (GPIO2.1 R39.1 U1.11), STEVAL-BMS114TX_Isolated SPI & MCU interface (R68.2)
ISOLm: STEVAL-BMS114TX_BMS Node (U3.4), STEVAL-BMS114TX_Isolated SPI & MCU interface (C81.2 ISOLm.1 T2.3)
ISOLp: STEVAL-BMS114TX_BMS Node (U3.6), STEVAL-BMS114TX_Isolated SPI & MCU interface (C27.2 ISOLp.1 T2.4)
